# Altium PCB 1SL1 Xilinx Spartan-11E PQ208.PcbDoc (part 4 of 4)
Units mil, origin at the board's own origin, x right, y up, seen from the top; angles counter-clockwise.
Board outline 7086.61 x 1988.19 mil, 2 copper layers (Top Layer, Bottom Layer), stack 29.698 mil thick; 115 components, 126 nets, 642 pads, 225 vias.
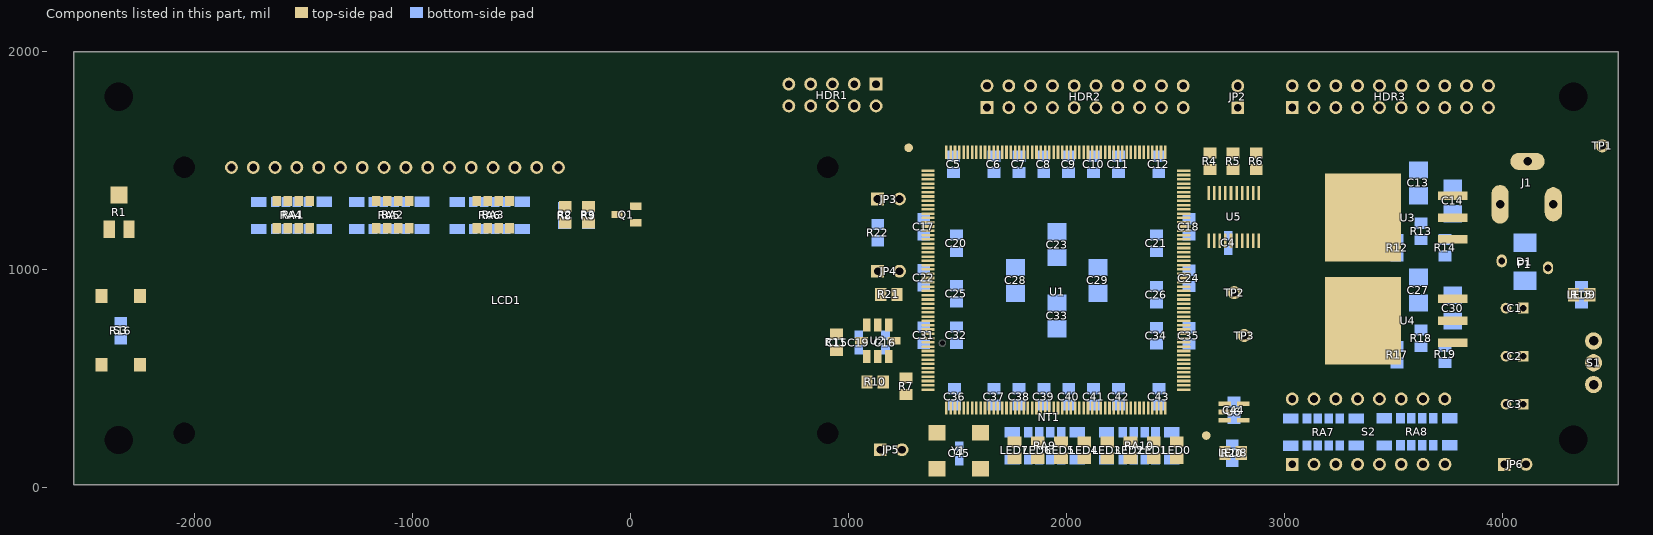
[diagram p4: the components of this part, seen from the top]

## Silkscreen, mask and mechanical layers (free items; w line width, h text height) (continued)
23_CONTINUATION_BLOCK:
  region: -5050,1550 -5120,1550 -5120,1500
  region: -5050,1550 -5120,1550 -5120,1600
  region: 9550,1550 9620,1550 9620,1600
  region: 9550,1550 9620,1550 9620,1500
  region: 2250,-3000 2250,-3070 2300,-3070
  region: 2250,-3000 2250,-3070 2200,-3070
  region: 2250,6100 2250,6170 2200,6170
  region: 2250,6100 2250,6170 2300,6170
  lines w5: -5250,-825 -5050,-825 ; -5250,1550 -5050,1550 ; -5250,3925 -5050,3925 ; -2750,-3200 -2750,-3000 ; -2750,6100 -2750,6300 ; -250,-3200 -250,-3000 ; -250,6100 -250,6300 ; 2250,-3200 2250,-3000 ; 2250,6100 2250,6300 ; 4750,-3200 4750,-3000 ; 4750,6100 4750,6300 ; 5050,-3000 9550,-3000 ; 5755,5575 9548,5575 ; 5755,5705 9548,5705 ; 5755,5835 9548,5835 ; 5755,5965 9548,5965 ; 5755,6095 5755,5445 9548,5445 ; 6055,5445 6055,5965 ; 6140,6100 6140,6249 7250,6249 7250,6100 7250,6300 ; 6355,5445 6355,5965 ; 6445,-3000 6445,-2850 ; 6750,-2850 6750,-2535 ; 7050,-3000 7050,-2850 ; 7140,6100 7140,6249 ; 7250,-3200 7250,-3000 ; 7750,-2850 7750,-2535 ; 8355,5445 8355,5965 ; 8790,-3000.1 8790,-2850.1 ; 8955,5445 8955,5965 ; 9250,-2850 9250,-2535 ; 9550,-2850 6445,-2850 ; 9550,-2535 6445,-2535 6445,-2850 ; 9550,-1800 9550,-3000 ; 9550,-1420 9699,-1420 9699,-310 9550,-310 ; 9550,-1310 9699,-1310 ; 9550,1550 9750,1550 ; 9550,3925 9750,3925 ; 9699,-825 9750,-825 ; -5050,-3000 -5050,-2804 -2173,-2804 -2173,-3000 -5050,-3000 ; -5050,-3000 9550,-3000 ; -5050,-3000 -5050,6100 ; -5050,6100 -5050,5770 -2990,5770 -2990,6100 -5050,6100 ; -5050,6100 9550,6100 9550,-3000 ; -5250,-3200 9750,-3200 9750,6300 -5250,6300 -5250,-3200
  text "DWG. NO." at 6155.1,6215 h30
  text "REV:" at 7165.1,6215 h30
  text "1" at -4018.66,6170 h70
  text "2" at -1523,6170 h70
  text "3" at 966.34,6170 h70
  text "4" at 3473.01,6170 h70
  text "5" at 5972,6170 h70
  text "6" at 8477,6170 h70
  text ".PCB_DWG_NO" at 6370,6125 h50
  text ".PCB_REV" at 7180,6125 h50
  text "T" at -5038,6027.61 h76
  text "H" at -4994.66,6027.61 h76
  text "I" at -4944.64,6027.61 h76
  text "S" at -4924.64,6027.61 h76
  text "D" at -4859.62,6027.61 h76
  text "O" at -4809.61,6027.61 h76
  text "C" at -4754.6,6027.61 h76
  text "U" at -4704.59,6027.61 h76
  text "M" at -4654.57,6027.61 h76
  text "E" at -4596.23,6027.61 h76
  text "N" at -4549.55,6027.61 h76
  text "T" at -4501.2,6027.61 h76
  text "A" at -4437.85,6027.61 h76
  text "N" at -4391.17,6027.61 h76
  text "D" at -4341.16,6027.61 h76
  text "T" at -4272.81,6027.61 h76
  text "H" at -4229.47,6027.61 h76
  text "E" at -4179.46,6027.61 h76
  text "D" at -4114.44,6027.61 h76
  text "A" at -4064.43,6027.61 h76
  text "T" at -4017.75,6027.61 h76
  text "A" at -3976.07,6027.61 h76
  text "D" at -3909.39,6027.61 h76
  text "I" at -3859.38,6027.61 h76
  text "S" at -3841.04,6027.61 h76
  text "C" at -3794.36,6027.61 h76
  text "L" at -3744.35,6027.61 h76
  text "O" at -3706.01,6027.61 h76
  text "S" at -3650.99,6027.61 h76
  text "E" at -3604.31,6027.61 h76
  text "D" at -3557.64,6027.61 h76
  text "H" at -3489.29,6027.61 h76
  text "E" at -3439.27,6027.61 h76
  text "R" at -3392.6,6027.61 h76
  text "E" at -3344.25,6027.61 h76
  text "I" at -3297.57,6027.61 h76
  text "N" at -3277.57,6027.61 h76
  text "O" at -3209.22,6027.61 h76
  text "R" at -3154.2,6027.61 h76
  text "REVISIONS" at 7390,5995 h60
  text "H" at -5038,5947.59 h76
  text "E" at -4987.99,5947.59 h76
  text "R" at -4941.31,5947.59 h76
  text "E" at -4891.3,5947.59 h76
  text "W" at -4846.29,5947.59 h76
  text "I" at -4777.94,5947.59 h76
  text "T" at -4759.6,5947.59 h76
  text "H" at -4716.25,5947.59 h76
  text "I" at -4647.9,5947.59 h76
  text "S" at -4627.9,5947.59 h76
  text "T" at -4562.88,5947.59 h76
  text "H" at -4519.54,5947.59 h76
  text "E" at -4469.53,5947.59 h76
  text "P" at -4404.51,5947.59 h76
  text "R" at -4357.83,5947.59 h76
  text "O" at -4307.82,5947.59 h76
  text "P" at -4253.77,5947.59 h76
  text "E" at -4207.1,5947.59 h76
  text "R" at -4160.42,5947.59 h76
  text "T" at -4112.07,5947.59 h76
  text "Y" at -4068.73,5947.59 h76
  text "O" at -4003.71,5947.59 h76
  text "F" at -3950.37,5947.59 h76
  text "A" at -3887.02,5947.59 h76
  text "L" at -3840.34,5947.59 h76
  text "T" at -3803.66,5947.59 h76
  text "I" at -3760.32,5947.59 h76
  text "U" at -3740.31,5947.59 h76
  text "M" at -3690.3,5947.59 h76
  text "L" at -3613.62,5947.59 h76
  text "I" at -3575.27,5947.59 h76
  text "M" at -3555.27,5947.59 h76
  text "I" at -3498.59,5947.59 h76
  text "T" at -3478.58,5947.59 h76
  text "E" at -3435.24,5947.59 h76
  text "D" at -3388.56,5947.59 h76
  text "A" at -3320.21,5947.59 h76
  text "N" at -3273.53,5947.59 h76
  text "D" at -3223.52,5947.59 h76
  text "M" at -3153.5,5947.59 h76
  text "A" at -3095.15,5947.59 h76
  text "Y" at -3050.14,5947.59 h76
  text "ZONE" at 5805,5870 h60
  text "REV" at 6135,5870 h60
  text "DATE" at 8555,5870 h60
  text "B" at -5038,5867.57 h76
  text "E" at -4991.32,5867.57 h76
  text "F" at -4924.64,5867.57 h76
  text "R" at -4881.3,5867.57 h76
  text "E" at -4831.28,5867.57 h76
  text "E" at -4786.27,5867.57 h76
  text "L" at -4739.59,5867.57 h76
  text "Y" at -4701.25,5867.57 h76
  text "D" at -4634.57,5867.57 h76
  text "I" at -4584.56,5867.57 h76
  text "S" at -4566.22,5867.57 h76
  text "T" at -4519.54,5867.57 h76
  text "R" at -4476.89,5867.57 h76
  text "I" at -4428.54,5867.57 h76
  text "B" at -4408.54,5867.57 h76
  text "U" at -4361.86,5867.57 h76
  text "T" at -4311.85,5867.57 h76
  text "E" at -4268.5,5867.57 h76
  text "D" at -4221.82,5867.57 h76
  text "I" at -4153.47,5867.57 h76
  text "N" at -4133.47,5867.57 h76
  text "W" at -4066.79,5867.57 h76
  text "H" at -3998.44,5867.57 h76
  text "O" at -3950.09,5867.57 h76
  text "L" at -3895.08,5867.57 h76
  text "E" at -3856.73,5867.57 h76
  text "." at -3810.06,5867.57 h76
  text "N" at -3771.71,5867.57 h76
  text "O" at -3721.7,5867.57 h76
  text "R" at -3646.68,5867.57 h76
  text "I" at -3598.34,5867.57 h76
  text "G" at -3578.33,5867.57 h76
  text "H" at -3523.32,5867.57 h76
  text "T" at -3474.97,5867.57 h76
  text "S" at -3431.63,5867.57 h76
  text "A" at -3366.61,5867.57 h76
  text "R" at -3319.94,5867.57 h76
  text "E" at -3269.92,5867.57 h76
  text "DESCRIPTION" at 7150,5865 h60
  text "APPROVED" at 9060,5865 h60
  text "R" at -5038,5787.55 h76
  text "E" at -4987.99,5787.55 h76
  text "S" at -4941.31,5787.55 h76
  text "E" at -4894.63,5787.55 h76
  text "R" at -4847.95,5787.55 h76
  text "V" at -4797.94,5787.55 h76
  text "E" at -4751.26,5787.55 h76
  text "D" at -4704.59,5787.55 h76
  text "O" at -4636.24,5787.55 h76
  text "R" at -4581.22,5787.55 h76
  text "E" at -4511.2,5787.55 h76
  text "X" at -4464.53,5787.55 h76
  text "P" at -4419.52,5787.55 h76
  text "R" at -4372.84,5787.55 h76
  text "E" at -4322.82,5787.55 h76
  text "S" at -4276.15,5787.55 h76
  text "S" at -4229.47,5787.55 h76
  text "O" at -4164.45,5787.55 h76
  text "R" at -4109.44,5787.55 h76
  text "I" at -4041.09,5787.55 h76
  text "M" at -4021.08,5787.55 h76
  text "P" at -3962.74,5787.55 h76
  text "L" at -3916.06,5787.55 h76
  text "I" at -3879.38,5787.55 h76
  text "E" at -3859.38,5787.55 h76
  text "D" at -3812.7,5787.55 h76
  text "W" at -3746.02,5787.55 h76
  text "A" at -3677.67,5787.55 h76
  text "R" at -3630.99,5787.55 h76
  text "A" at -3580.98,5787.55 h76
  text "N" at -3534.3,5787.55 h76
  text "T" at -3485.95,5787.55 h76
  text "E" at -3442.61,5787.55 h76
  text "E" at -3395.93,5787.55 h76
  text "G" at -3334.68,5787.55 h76
  text "I" at -3279.67,5787.55 h76
  text "V" at -3259.66,5787.55 h76
  text "E" at -3212.98,5787.55 h76
  text "N" at -3166.3,5787.55 h76
  text "." at -3117.96,5787.55 h76
  text "A" at 6165,5735 h60
  text "ORIGINAL" at 7225,5735 h60
  text "A" at -5175,5027 h70
  text "A" at 9625,5027 h70
  text "B" at -5175,2647 h70
  text "B" at 9625,2647 h70
  text "C" at -5175,272 h70
  text "C" at 9625,272 h70
  text "DWG. NO." at 9665,-325.1 h30 r270
  text ".PCB_DWG_NO" at 9575,-540 h50 r270
  text "REV:" at 9665,-1335.1 h30 r270
  text ".PCB_REV" at 9575,-1350 h50 r270
  text "D" at -5175,-2098 h70
  text "D" at 9625,-2098 h70
  text "SIZE:" at 6530,-2610 h45
  text "CAGE CODE:" at 6775,-2610 h45
  text "DWG NO:" at 7775,-2610 h45
  text "REV:" at 9335,-2610 h45
  text ".PCB_DWG_NO" at 8085,-2750 h100
  text "B" at 6570,-2755 h100
  text ".PCB_REV" at 9365,-2755 h100
  text ".CAGE_CODE" at 6945,-2765 h100
  text "SCALE:" at 6470,-2925 h45
  text "FILE NAME:" at 7075,-2925.1 h45
  text "SHEET:" at 8815,-2925.1 h45
  text ".Printout_Name" at -4994,-2947 h150
  text ".PCB_FILE_NAME_NO_PATH" at 7418,-2970.1 h60
  text ".PCB_SCALE" at 6740,-2975 h60
  text "OF" at 9265,-2975.1 h45
  text "DOC-104 REV A" at -5050,-3042.1 h20
  text "1" at -4018.66,-3130 h70
  text "2" at -1523,-3130 h70
  text "3" at 966.34,-3130 h70
  text "4" at 3473.01,-3130 h70
  text "5" at 5972,-3130 h70
  text "6" at 8477,-3130 h70
24_CONTINUATION_BLOCK_MIRRORED:
  region: 2250,6100 2250,6170 2200,6170
  region: 2250,6100 2250,6170 2300,6170
  region: 2250,-3000 2250,-3070 2300,-3070
  region: 2250,-3000 2250,-3070 2200,-3070
  region: -5050,1550 -5120,1550 -5120,1500
  region: -5050,1550 -5120,1550 -5120,1600
  region: 9550,1550 9620,1550 9620,1600
  region: 9550,1550 9620,1550 9620,1500
  lines w5: -5250,-825 -5199,-825 ; -5250,1550 -5050,1550 ; -5250,3925 -5050,3925 ; -5199,-1310 -5050,-1310 ; -5050,-2850 -1945,-2850 ; -5050,-2535 -1945,-2535 -1945,-2850 ; -5050,-1800 -5050,-3000 ; -5050,-1420 -5199,-1420 -5199,-310 -5050,-310 ; -5048,5445 -1255,5445 -1255,6095 ; -5048,5575 -1255,5575 ; -5048,5705 -1255,5705 ; -5048,5835 -1255,5835 ; -5048,5965 -1255,5965 ; -4750,-2850 -4750,-2535 ; -4455,5445 -4455,5965 ; -4290,-3000.1 -4290,-2850.1 ; -3855,5445 -3855,5965 ; -3250,-2850 -3250,-2535 ; -2750,-3200 -2750,-3000 ; -2750,6300 -2750,6100 -2750,6249 -1640,6249 -1640,6100 ; -2640,6100 -2640,6249 ; -2550,-3000 -2550,-2850 ; -2250,-2850 -2250,-2535 ; -1945,-3000 -1945,-2850 ; -1855,5445 -1855,5965 ; -1555,5445 -1555,5965 ; -550,-3000 -5050,-3000 ; -250,-3200 -250,-3000 ; -250,6100 -250,6300 ; 2250,-3200 2250,-3000 ; 2250,6100 2250,6300 ; 4750,-3200 4750,-3000 ; 4750,6100 4750,6300 ; 7250,-3200 7250,-3000 ; 7250,6100 7250,6300 ; 9550,-825 9750,-825 ; 9550,1550 9750,1550 ; 9550,3925 9750,3925 ; -5050,-3000 -5050,6100 9550,6100 ; -5050,-3000 9550,-3000 ; 9550,-3000 6673,-3000 6673,-2804 9550,-2804 9550,-3000 ; 9550,-3000 9550,6100 ; 9550,6100 9550,5770 7490,5770 7490,6100 9550,6100 ; -5250,-3200 -5250,6300 9750,6300 9750,-3200 -5250,-3200
  text "REV:" at -2665.1,6215 h30
  text "DWG. NO." at -1655.1,6215 h30
  text "6" at -3977,6170 h70
  text "5" at -1472,6170 h70
  text "4" at 1026.99,6170 h70
  text "3" at 3533.66,6170 h70
  text "2" at 6023,6170 h70
  text "1" at 8518.66,6170 h70
  text ".PCB_REV" at -2680,6125 h50
  text ".PCB_DWG_NO" at -1870,6125 h50
  text "R" at 7654.2,6027.61 h76
  text "O" at 7709.22,6027.61 h76
  text "N" at 7777.57,6027.61 h76
  text "I" at 7797.57,6027.61 h76
  text "E" at 7844.25,6027.61 h76
  text "R" at 7892.59,6027.61 h76
  text "E" at 7939.27,6027.61 h76
  text "H" at 7989.29,6027.61 h76
  text "D" at 8057.64,6027.61 h76
  text "E" at 8104.31,6027.61 h76
  text "S" at 8150.99,6027.61 h76
  text "O" at 8206.01,6027.61 h76
  text "L" at 8244.35,6027.61 h76
  text "C" at 8294.36,6027.61 h76
  text "S" at 8341.04,6027.61 h76
  text "I" at 8359.38,6027.61 h76
  text "D" at 8409.39,6027.61 h76
  text "A" at 8476.07,6027.61 h76
  text "T" at 8517.75,6027.61 h76
  text "A" at 8564.43,6027.61 h76
  text "D" at 8614.44,6027.61 h76
  text "E" at 8679.45,6027.61 h76
  text "H" at 8729.47,6027.61 h76
  text "T" at 8772.81,6027.61 h76
  text "D" at 8841.16,6027.61 h76
  text "N" at 8891.17,6027.61 h76
  text "A" at 8937.85,6027.61 h76
  text "T" at 9001.2,6027.61 h76
  text "N" at 9049.55,6027.61 h76
  text "E" at 9096.22,6027.61 h76
  text "M" at 9154.57,6027.61 h76
  text "U" at 9204.58,6027.61 h76
  text "C" at 9254.6,6027.61 h76
  text "O" at 9309.61,6027.61 h76
  text "D" at 9359.62,6027.61 h76
  text "S" at 9424.64,6027.61 h76
  text "I" at 9444.64,6027.61 h76
  text "H" at 9494.66,6027.61 h76
  text "T" at 9538,6027.61 h76
  text "REVISIONS" at -2890,5995 h60
  text "Y" at 7550.14,5947.59 h76
  text "A" at 7595.15,5947.59 h76
  text "M" at 7653.5,5947.59 h76
  text "D" at 7723.52,5947.59 h76
  text "N" at 7773.53,5947.59 h76
  text "A" at 7820.21,5947.59 h76
  text "D" at 7888.56,5947.59 h76
  text "E" at 7935.24,5947.59 h76
  text "T" at 7978.58,5947.59 h76
  text "I" at 7998.59,5947.59 h76
  text "M" at 8055.27,5947.59 h76
  text "I" at 8075.27,5947.59 h76
  text "L" at 8113.61,5947.59 h76
  text "M" at 8190.3,5947.59 h76
  text "U" at 8240.31,5947.59 h76
  text "I" at 8260.32,5947.59 h76
  text "T" at 8303.66,5947.59 h76
  text "L" at 8340.34,5947.59 h76
  text "A" at 8387.02,5947.59 h76
  text "F" at 8450.36,5947.59 h76
  text "O" at 8503.71,5947.59 h76
  text "Y" at 8568.73,5947.59 h76
  text "T" at 8612.07,5947.59 h76
  text "R" at 8660.42,5947.59 h76
  text "E" at 8707.09,5947.59 h76
  text "P" at 8753.77,5947.59 h76
  text "O" at 8807.82,5947.59 h76
  text "R" at 8857.83,5947.59 h76
  text "P" at 8904.51,5947.59 h76
  text "E" at 8969.53,5947.59 h76
  text "H" at 9019.54,5947.59 h76
  text "T" at 9062.88,5947.59 h76
  text "S" at 9127.9,5947.59 h76
  text "I" at 9147.9,5947.59 h76
  text "H" at 9216.25,5947.59 h76
  text "T" at 9259.6,5947.59 h76
  text "I" at 9277.94,5947.59 h76
  text "W" at 9346.29,5947.59 h76
  text "E" at 9391.3,5947.59 h76
  text "R" at 9441.31,5947.59 h76
  text "E" at 9487.99,5947.59 h76
  text "H" at 9538,5947.59 h76
  text "DATE" at -4055,5870 h60
  text "REV" at -1635,5870 h60
  text "ZONE" at -1305,5870 h60
  text "E" at 7769.92,5867.57 h76
  text "R" at 7819.93,5867.57 h76
  text "A" at 7866.61,5867.57 h76
  text "S" at 7931.63,5867.57 h76
  text "T" at 7974.97,5867.57 h76
  text "H" at 8023.32,5867.57 h76
  text "G" at 8078.33,5867.57 h76
  text "I" at 8098.34,5867.57 h76
  text "R" at 8146.68,5867.57 h76
  text "O" at 8221.7,5867.57 h76
  text "N" at 8271.71,5867.57 h76
  text "." at 8310.06,5867.57 h76
  text "E" at 8356.73,5867.57 h76
  text "L" at 8395.08,5867.57 h76
  text "O" at 8450.09,5867.57 h76
  text "H" at 8498.43,5867.57 h76
  text "W" at 8566.78,5867.57 h76
  text "N" at 8633.47,5867.57 h76
  text "I" at 8653.47,5867.57 h76
  text "D" at 8721.82,5867.57 h76
  text "E" at 8768.5,5867.57 h76
  text "T" at 8811.85,5867.57 h76
  text "U" at 8861.86,5867.57 h76
  text "B" at 8908.54,5867.57 h76
  text "I" at 8928.54,5867.57 h76
  text "R" at 8976.89,5867.57 h76
  text "T" at 9019.54,5867.57 h76
  text "S" at 9066.22,5867.57 h76
  text "I" at 9084.55,5867.57 h76
  text "D" at 9134.57,5867.57 h76
  text "Y" at 9201.25,5867.57 h76
  text "L" at 9239.59,5867.57 h76
  text "E" at 9286.27,5867.57 h76
  text "E" at 9331.28,5867.57 h76
  text "R" at 9381.29,5867.57 h76
  text "F" at 9424.64,5867.57 h76
  text "E" at 9491.32,5867.57 h76
  text "B" at 9538,5867.57 h76
  text "APPROVED" at -4560,5865 h60
  text "DESCRIPTION" at -2650,5865 h60
  text "." at 7617.96,5787.55 h76
  text "N" at 7666.3,5787.55 h76
  text "E" at 7712.98,5787.55 h76
  text "V" at 7759.66,5787.55 h76
  text "I" at 7779.66,5787.55 h76
  text "G" at 7834.68,5787.55 h76
  text "E" at 7895.93,5787.55 h76
  text "E" at 7942.61,5787.55 h76
  text "T" at 7985.95,5787.55 h76
  text "N" at 8034.3,5787.55 h76
  text "A" at 8080.97,5787.55 h76
  text "R" at 8130.99,5787.55 h76
  text "A" at 8177.66,5787.55 h76
  text "W" at 8246.01,5787.55 h76
  text "D" at 8312.7,5787.55 h76
  text "E" at 8359.38,5787.55 h76
  text "I" at 8379.38,5787.55 h76
  text "L" at 8416.06,5787.55 h76
  text "P" at 8462.74,5787.55 h76
  text "M" at 8521.08,5787.55 h76
  text "I" at 8541.09,5787.55 h76
  text "R" at 8609.44,5787.55 h76
  text "O" at 8664.45,5787.55 h76
  text "S" at 8729.47,5787.55 h76
  text "S" at 8776.15,5787.55 h76
  text "E" at 8822.82,5787.55 h76
  text "R" at 8872.84,5787.55 h76
  text "P" at 8919.51,5787.55 h76
  text "X" at 8964.53,5787.55 h76
  text "E" at 9011.2,5787.55 h76
  text "R" at 9081.22,5787.55 h76
  text "O" at 9136.23,5787.55 h76
  text "D" at 9204.58,5787.55 h76
  text "E" at 9251.26,5787.55 h76
  text "V" at 9297.94,5787.55 h76
  text "R" at 9347.95,5787.55 h76
  text "E" at 9394.63,5787.55 h76
  text "S" at 9441.31,5787.55 h76
  text "E" at 9487.99,5787.55 h76
  text "R" at 9538,5787.55 h76
  text "ORIGINAL" at -2725,5735 h60
  text "A" at -1665,5735 h60
  text "A" at -5125,5027 h70
  text "A" at 9675,5027 h70
  text "B" at -5125,2647 h70
  text "B" at 9675,2647 h70
  text "C" at -5125,272 h70
  text "C" at 9675,272 h70
  text "DWG. NO." at -5165,-325.1 h30 r90
  text ".PCB_DWG_NO" at -5075,-540 h50 r90
  text "REV:" at -5165,-1335.1 h30 r90
  text ".PCB_REV" at -5075,-1350 h50 r90
  text "D" at -5125,-2098 h70
  text "D" at 9675,-2098 h70
  text "REV:" at -4835,-2610 h45
  text "DWG NO:" at -3275,-2610 h45
  text "CAGE CODE:" at -2275,-2610 h45
  text "SIZE:" at -2030,-2610 h45
  text ".PCB_DWG_NO" at -3585,-2750 h100
  text ".PCB_REV" at -4865,-2755 h100
  text "B" at -2070,-2755 h100
  text ".CAGE_CODE" at -2445,-2765 h100
  text "SHEET:" at -4315,-2925.1 h45
  text "FILE NAME:" at -2575,-2925.1 h45
  text "SCALE:" at -1970,-2925 h45
  text ".Printout_Name" at 9494,-2947 h150
  text ".PCB_FILE_NAME_NO_PATH" at -2918,-2970.1 h60
  text "OF" at -4765,-2975.1 h45
  text ".PCB_SCALE" at -2240,-2975 h60
  text "DOC-104 REV A" at 9550,-3042.1 h20
  text "6" at -3977,-3130 h70
  text "5" at -1472,-3130 h70
  text "4" at 1026.99,-3130 h70
  text "3" at 3533.66,-3130 h70
  text "2" at 6023,-3130 h70
  text "1" at 8518.66,-3130 h70

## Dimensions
-2555.06,9.66 to 4531.55,9.66 on 2_DIMENSION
